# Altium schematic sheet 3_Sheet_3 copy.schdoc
size 302 x 215 mm; Name: A_A4; Symbol: A_A4; Device: A_A4; @Project Name: Quectel_EC200U_Board_2024-07-11; REV: 1.1; Date: 11-07-24; Sheet: 1/1; Draw By: Anusha; Company: FervidSmart Solutions; Convert to PCB: yes; Add into BOM: yes
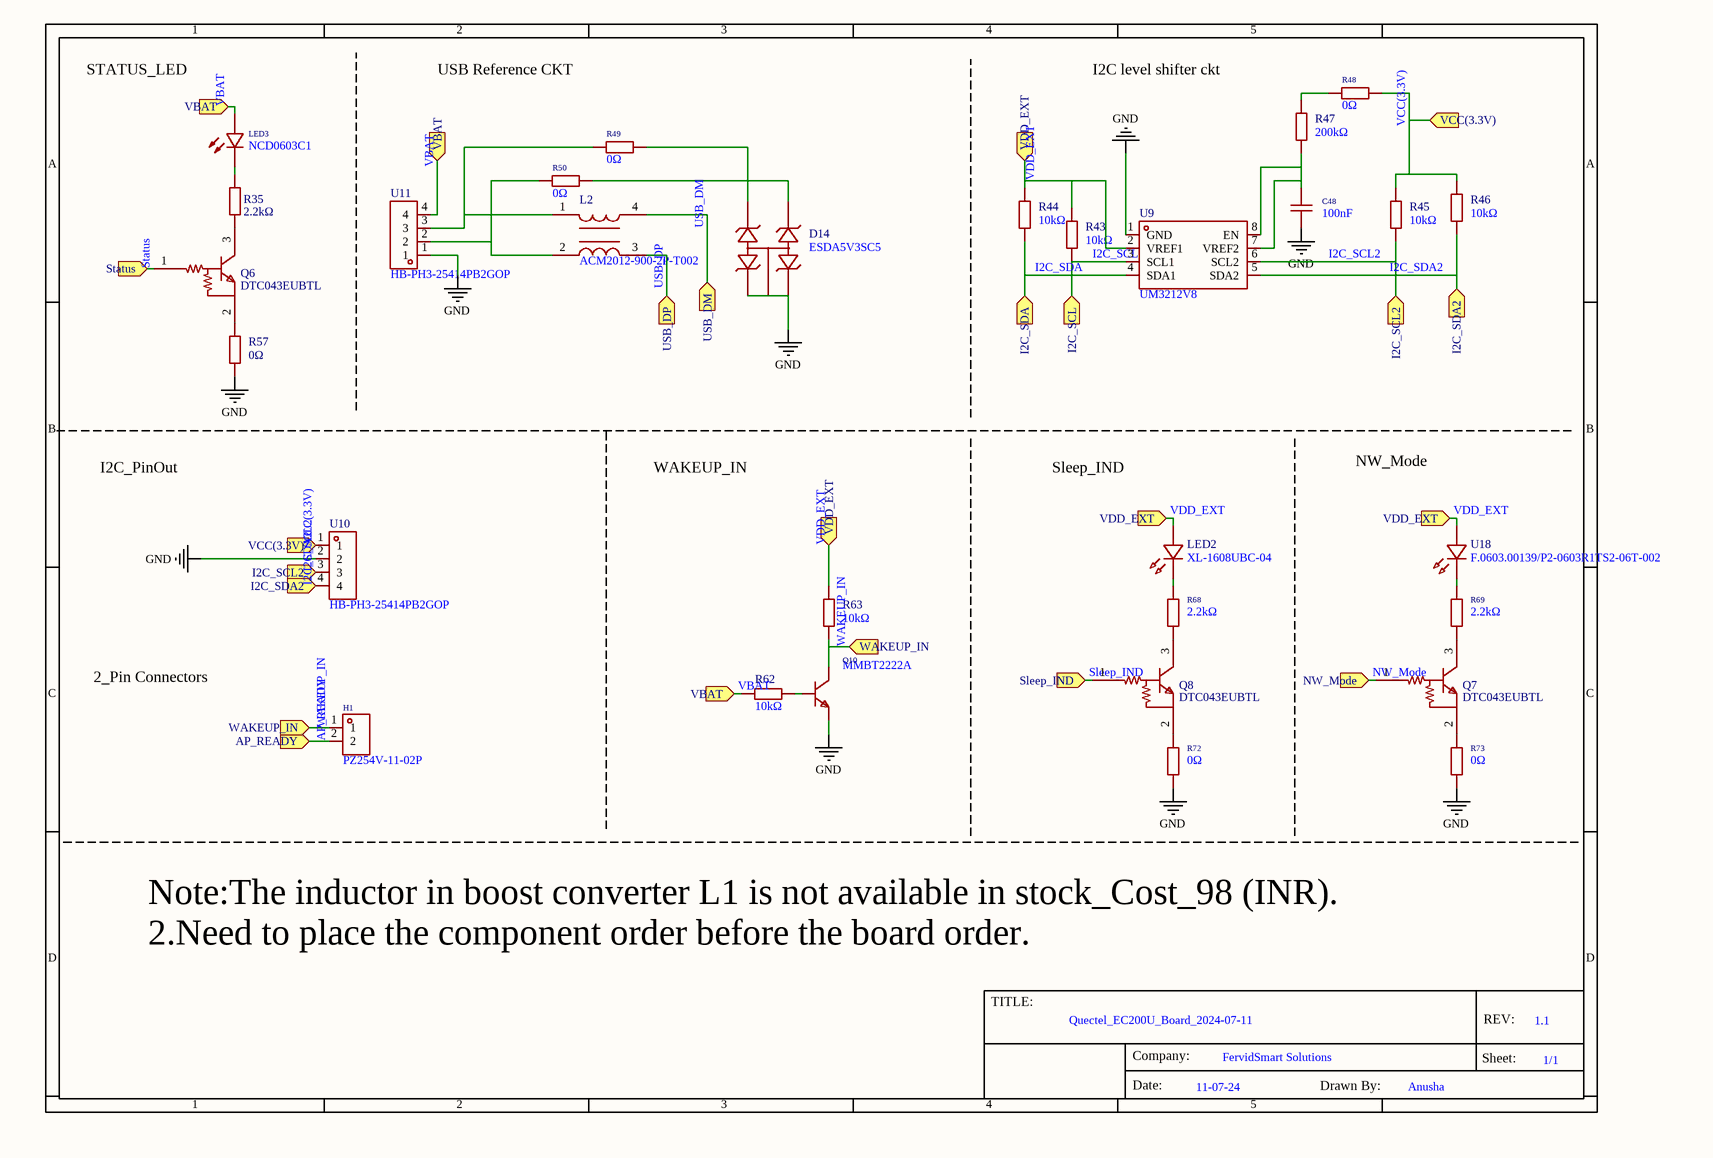
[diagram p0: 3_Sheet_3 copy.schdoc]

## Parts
C48  100nF  [C0603]
D14  ESDA5V3SC5  [SOT-23-5_L3.0-W1.7-P0.95-LS2.8-BR]
H1  PZ254V-11-02P  [HDR-TH_2P-P2.54-V-M]
L2  ACM2012-900-2P-T002  [IND-SMD_4P-L2.0-W1.2-TL]
LED2  XL-1608UBC-04  [LED0603-RD_BLUE]
LED3  NCD0603C1  [LED0603-RD]
Q6  DTC043EUBTL  [SOT-323-3_L2.0-W1.3-P1.30-LS2.1-BR]
Q7  DTC043EUBTL  [SOT-323-3_L2.0-W1.3-P1.30-LS2.1-BR]
Q8  DTC043EUBTL  [SOT-323-3_L2.0-W1.3-P1.30-LS2.1-BR]
Q10  MMBT2222A  [SOT-23-3_L2.9-W1.3-P1.90-LS2.4-BR]
R35  2.2kΩ  [R0603]
R43  10kΩ  [R0603]
R44  10kΩ  [R0603]
R45  10kΩ  [R0603]
R46  10kΩ  [R0603]
R47  200kΩ  [R0603]
R48  0Ω  [R0603]
R49  0Ω  [R0603]
R50  0Ω  [R0603]
R57  0Ω  [R0603]
R62  10kΩ  [R0603]
R63  10kΩ  [R0603]
R68  2.2kΩ  [R0603]
R69  2.2kΩ  [R0603]
R72  0Ω  [R0603]
R73  0Ω  [R0603]
U9  UM3212V8  [VSSOP-8_L2.3-W2.0-P0.50-LS3.1-BL]
U10  HB-PH3-25414PB2GOP  [HDR-TH_4P-P2.54-V-M]
U11  HB-PH3-25414PB2GOP  [HDR-TH_4P-P2.54-V-M]
U18  F.0603.00139/P2-0603R1TS2-06T-002  [LED0603-RD]

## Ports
AP_READY (in), I2C_SCL2 (in), I2C_SCL (in), I2C_SDA2 (in), I2C_SDA (in), NW_Mode (in), Sleep_IND (in), Status (in), USB_DM (in), USB_DP (in), VBAT (in), VCC(3.3V) (in), VDD_EXT (in), WAKEUP_IN (in)

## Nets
GND: C48.1 D14.1 D14.2 D14.3 Q10.2(E) R57.1 R72.1 R73.1 U9.1(GND) U10.2 U11.1
AP_READY: H1.2 ; port AP_READY
I2C_SCL: R43.1 U9.3(SCL1) ; port I2C_SCL
I2C_SCL2: R45.1 U9.6(SCL2) U10.3 ; port I2C_SCL2
I2C_SDA: R44.1 U9.4(SDA1) ; port I2C_SDA
I2C_SDA2: R46.1 U9.5(SDA2) U10.4 ; port I2C_SDA2
NW_Mode: Q7.1(B) ; port NW_Mode
Sleep_IND: Q8.1(B) ; port Sleep_IND
Status: Q6.1(B) ; port Status
USB_DM: L2.4 ; port USB_DM
USB_DP: L2.3 ; port USB_DP
VBAT: LED3.2(+) R62.2 U11.4 ; port VBAT
VCC(3.3V): R45.2 R46.2 R48.2 U10.1 ; port VCC(3.3V)
VDD_EXT: LED2.2(A) R43.2 R44.2 R63.1 U9.2(VREF1) U18.2(A) ; port VDD_EXT
WAKEUP_IN: H1.1 Q10.3(C) R63.2 ; port WAKEUP_IN
NetC48_2: C48.2 R47.1 U9.7(VREF2) U9.8(EN)
NetD14_4: D14.4 R50.2
NetD14_5: D14.5 R49.2
NetL2_1: L2.1 R49.1 U11.3
NetL2_2: L2.2 R50.1 U11.2
NetLED2_1: LED2.1(K) R68.2
NetLED3_1: LED3.1(-) R35.1
NetQ6_2: Q6.2(E) R57.2
NetQ6_3: Q6.3(C) R35.2
NetQ7_2: Q7.2(E) R73.2
NetQ7_3: Q7.3(C) R69.1
NetQ8_2: Q8.2(E) R72.2
NetQ8_3: Q8.3(C) R68.1
NetQ10_1: Q10.1(B) R62.1
NetR47_2: R47.2 R48.1
NetR69_2: R69.2 U18.1(K)

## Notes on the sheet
- STATUS_LED
- USB Reference CKT
- I2C level shifter ckt
- I2C_PinOut
- WAKEUP_IN
- Sleep_IND
- NW_Mode
- 2_Pin Connectors
- Note:The inductor in boost converter L1 is not available in stock_Cost_98 (INR).
  2.Need to place the component order before the board order.

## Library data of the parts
C48 = CL10B104JB8NNNC: Manufacturer: SAMSUNG(三星); Add into BOM: yes; Tolerance: ±5%
D14 = ESDA5V3SC5: Manufacturer: ST(意法半导体); Add into BOM: yes; polarity: Unidirectional; Reverse Stand-Off Voltage (Vrwm): 3V; Maximum Clamping Voltage: 5.3V; Peak Pulse Power Dissipation (Ppp)@10/1000us: 500W; Number of Lines: Quad; Type: ESD
H1 = PZ254V-11-02P: Manufacturer: XFCN(兴飞); Add into BOM: no; Convert to PCB: yes; Pin Structure: 1x2P; Pitch: 2.54mm; Circluar Pins/Square Pins: Square Pins
L2 = ACM2012-900-2P-T002: Manufacturer: TDK; Add into BOM: yes; Number of Lines: 2; Withstanding Voltage: 50V; Current Rating: 400mA; Impedance @ Frequency: 90Ω@100MHz; DC Resistance (DCR): 190mΩ
LED2 = XL-1608UBC-04: Manufacturer: XINGLIGHT(成兴光); Add into BOM: yes; Emitted Color: Blue; Power Dissipation: 80mW; Forward Current: 25mA; Dominant Wavelength: 460nm~469nm; Peak Wavelength: 475nm; Lens Color: 无色透明透镜; Viewing Angle: 120°; Mounting Sytle: Positive post
LED3 = NCD0603C1: Manufacturer: 国星光电; Symbol: FC-D1608HGK-572C; Add into BOM: yes; Emitted Color: Green-yellow; Forward Voltage (VF): 1.6V~2.6V; Power Dissipation: 65mW; Forward Current: 5mA; Dominant Wavelength: 565nm~578nm; Lens Color: 无色透明透镜; Luminous Intensity: 5mcd~13mcd; Viewing Angle: 140°
Q6-Q8 = DTC043EUBTL: Manufacturer: ROHM Semicon; Convert to PCB: yes
Q10 = MMBT2222A_C83939: Manufacturer: ST(先科); Add into BOM: yes; DC Current Gain (hFE@Ic,Vce): 40@500mA,10V; Transition Frequency (fT): 300MHz; Collector Cut-Off Current (Icbo): 10nA; Collector-Emitter Saturation Voltage (VCE(sat)@Ic,Ib): 1V@500mA,50mA
R35 = RK73H1JTTD2201F: Manufacturer: KOA; Resistance: 2.2K; Convert to PCB: yes
R43-R46 R62 R63 = ARG03BTC1002: Manufacturer: Viking(光颉); Add into BOM: yes; Tolerance: ±0.1%; Temperature Coefficient: ±25ppm/℃
R47 = ARG03BTC2003: Manufacturer: Viking(光颉); Add into BOM: yes; Tolerance: ±0.1%; Temperature Coefficient: ±25ppm/℃
R48-R50 R72 R73 = 0603WAF0000T5E: Manufacturer: UNI-ROYAL(厚声); Add into BOM: yes; Tolerance: ±1%
R57 = RK73Z1JTTD: Manufacturer: KOA; Resistance: 0; Convert to PCB: yes
R68 R69 = 0603WAF2201T5E_C4190: Manufacturer: UNI-ROYAL(厚声); Add into BOM: yes; Tolerance: ±1%; Temperature Coefficient: ±100ppm/℃
U9 = UM3212V8: Manufacturer: Union(英联); Add into BOM: yes
U10 = HB-PH3-25414PB2GOP: Manufacturer: HANBO(汉博); Add into BOM: yes; Pin Structure: 1x4P; Pitch: 2.54mm; Circluar Pins/Square Pins: Square Pins; Current Rating (Max): 3A; Voltage Rating (Max): 250V; Soldering Temperature(Max): 260℃
U11 = HB-PH3-25414PB2GOP: Manufacturer: HANBO(汉博); Add into BOM: no; Convert to PCB: yes; Pin Structure: 1x4P; Pitch: 2.54mm; Circluar Pins/Square Pins: Square Pins; Current Rating (Max): 3A; Voltage Rating (Max): 250V; Soldering Temperature(Max): 260℃
U18 = F.0603.00139/P2-0603R1TS2-06T-002: Manufacturer: TUOZHAN(拓展光电); Add into BOM: yes; Emitted Color: Red; Forward Current: 5mA; Viewing Angle: 120°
